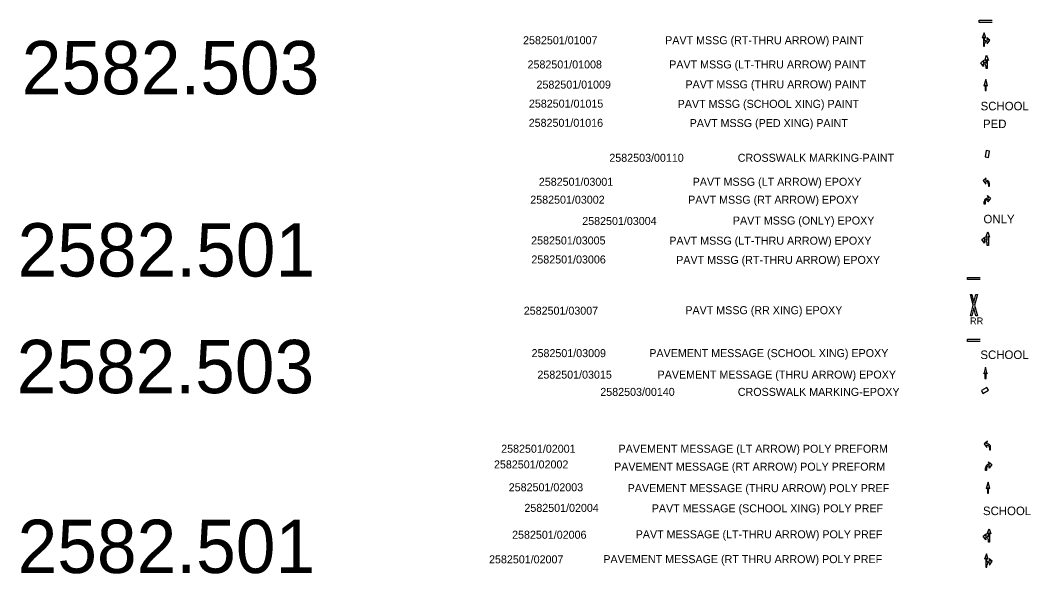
# Model space of a CAD drawing. Extents: x 2147716 to 2176321, y 2125040 to 2131750.
# Drawn here: x 2155871 to 2156818, y 2127335 to 2127855 of the extents above; entities that cross this region are included whole.
import ezdxf

# ---------------------------------------------------------------- set-up
doc = ezdxf.new("R2010")
doc.units = 0
doc.layers.add('DETAIL TXT', color=7, linetype='Continuous')
doc.layers.add('PVMT MARK', color=7, linetype='Continuous')

msp = doc.modelspace()

# ---------------------------------------------------------------- linework, layer by layer
at = {"layer": 'PVMT MARK'}
for p, q in [((2156769.69, 2127854.56), (2156781.69, 2127854.56)), ((2156769.69, 2127852.56), (2156769.69, 2127854.56)), ((2156781.69, 2127852.56), (2156769.69, 2127852.56)), ((2156774.26, 2127842.85), (2156772.52, 2127837.89)), ((2156772.52, 2127837.89), (2156773.76, 2127838.88)), ((2156773.76, 2127838.88), (2156773.76, 2127830.28)), ((2156775.99, 2127837.89), (2156774.26, 2127842.85)), ((2156774.75, 2127834.91), (2156774.75, 2127838.88)), ((2156774.75, 2127838.88), (2156775.99, 2127837.89)), ((2156776.9, 2127834.41), (2156777.57, 2127834.41)), ((2156779.72, 2127835.74), (2156776.97, 2127838.05)), ((2156776.97, 2127838.05), (2156777.63, 2127835.98)), ((2156777.63, 2127835.98), (2156776.97, 2127835.98)), ((2156777.23, 2127832.26), (2156779.72, 2127835.74)), ((2156777.57, 2127834.41), (2156777.23, 2127832.26)), ((2156773.76, 2127830.28), (2156774.75, 2127830.28)), ((2156774.75, 2127830.28), (2156774.75, 2127832.26)), ((2156771.22, 2127814.69), (2156773.96, 2127817)), ((2156773.96, 2127817), (2156773.3, 2127814.94)), ((2156774.94, 2127816.84), (2156776.67, 2127821.8)), ((2156776.18, 2127817.83), (2156774.94, 2127816.84)), ((2156776.18, 2127813.86), (2156776.18, 2127817.83)), ((2156776.67, 2127821.8), (2156778.41, 2127816.84)), ((2156778.41, 2127816.84), (2156777.17, 2127817.83)), ((2156777.17, 2127817.83), (2156777.17, 2127809.23)), ((2156773.7, 2127811.22), (2156771.22, 2127814.69)), ((2156773.3, 2127814.94), (2156773.96, 2127814.94)), ((2156774.03, 2127813.37), (2156773.37, 2127813.37)), ((2156773.37, 2127813.37), (2156773.7, 2127811.22)), ((2156776.18, 2127809.23), (2156776.18, 2127811.22)), ((2156777.17, 2127809.23), (2156776.18, 2127809.23)), ((2156774.14, 2127792.88), (2156775.26, 2127794.01)), ((2156775.26, 2127794.01), (2156775.26, 2127788.55)), ((2156775.26, 2127788.55), (2156776.25, 2127788.55)), ((2156776.25, 2127788.55), (2156776.25, 2127794.01)), ((2156776.25, 2127794.01), (2156777.37, 2127792.93)), ((2156776.28, 2127706.86), (2156773.3, 2127704.38)), ((2156773.3, 2127704.38), (2156775.78, 2127700.91)), ((2156775.38, 2127704.58), (2156776.28, 2127706.86)), ((2156776.04, 2127704.58), (2156775.38, 2127704.58)), ((2156775.78, 2127700.91), (2156775.38, 2127703.02)), ((2156775.38, 2127703.02), (2156776.04, 2127703.02)), ((2156778.26, 2127700.91), (2156778.26, 2127698.92)), ((2156778.26, 2127698.92), (2156779.26, 2127698.92)), ((2156779.26, 2127698.92), (2156779.26, 2127701.4)), ((2156774.4, 2127682.12), (2156774.4, 2127684.6)), ((2156775.39, 2127684.11), (2156775.39, 2127682.12)), ((2156778.28, 2127687.78), (2156777.37, 2127690.06)), ((2156777.37, 2127690.06), (2156780.35, 2127687.58)), ((2156777.62, 2127687.78), (2156778.28, 2127687.78)), ((2156778.28, 2127686.22), (2156777.62, 2127686.22)), ((2156780.35, 2127687.58), (2156777.87, 2127684.11)), ((2156777.87, 2127684.11), (2156778.28, 2127686.22)), ((2156775.39, 2127682.12), (2156774.4, 2127682.12)), ((2156776.01, 2127651.05), (2156777.75, 2127656.01)), ((2156777.75, 2127656.01), (2156779.48, 2127651.05)), ((2156772.29, 2127648.9), (2156775.03, 2127651.21)), ((2156774.77, 2127645.42), (2156772.29, 2127648.9)), ((2156775.03, 2127651.21), (2156774.37, 2127649.14)), ((2156774.37, 2127649.14), (2156775.03, 2127649.14)), ((2156775.1, 2127647.57), (2156774.44, 2127647.57)), ((2156774.44, 2127647.57), (2156774.77, 2127645.42)), ((2156777.25, 2127652.04), (2156776.01, 2127651.05)), ((2156777.25, 2127648.07), (2156777.25, 2127652.04)), ((2156777.25, 2127643.44), (2156777.25, 2127645.42)), ((2156779.48, 2127651.05), (2156778.24, 2127652.04)), ((2156778.24, 2127652.04), (2156778.24, 2127643.44)), ((2156778.24, 2127643.44), (2156777.25, 2127643.44)), ((2156758.67, 2127613.32), (2156770.67, 2127613.32)), ((2156758.67, 2127611.32), (2156758.67, 2127613.32)), ((2156770.67, 2127611.32), (2156758.67, 2127611.32)), ((2156761.47, 2127597.32), (2156764.07, 2127587.32)), ((2156764.07, 2127587.32), (2156761.47, 2127597.32)), ((2156764.07, 2127587.32), (2156761.47, 2127597.32)), ((2156761.47, 2127597.32), (2156762.77, 2127597.32)), ((2156762.77, 2127597.32), (2156764.67, 2127589.82)), ((2156764.67, 2127589.82), (2156766.67, 2127597.32)), ((2156767.97, 2127597.32), (2156765.37, 2127587.32)), ((2156766.67, 2127597.32), (2156767.97, 2127597.32)), ((2156761.47, 2127577.32), (2156764.07, 2127587.32)), ((2156764.67, 2127584.82), (2156762.77, 2127577.32)), ((2156764.67, 2127587.32), (2156764.67, 2127587.32)), ((2156766.67, 2127577.32), (2156764.67, 2127584.82)), ((2156765.37, 2127587.32), (2156767.97, 2127577.32)), ((2156762.77, 2127577.32), (2156761.47, 2127577.32)), ((2156767.97, 2127577.32), (2156766.67, 2127577.32)), ((2156758.67, 2127555.32), (2156770.67, 2127555.32)), ((2156758.67, 2127553.32), (2156758.67, 2127555.32)), ((2156770.67, 2127553.32), (2156758.67, 2127553.32)), ((2156773.95, 2127523.01), (2156775.07, 2127524.13)), ((2156775.07, 2127524.13), (2156775.07, 2127518.67)), ((2156776.06, 2127518.67), (2156776.06, 2127524.13)), ((2156776.06, 2127524.13), (2156777.19, 2127523.06)), ((2156775.07, 2127518.67), (2156776.06, 2127518.67)), ((2156777.41, 2127459.69), (2156774.44, 2127457.21)), ((2156774.44, 2127457.21), (2156776.92, 2127453.74)), ((2156776.51, 2127457.41), (2156777.41, 2127459.69)), ((2156777.17, 2127457.41), (2156776.51, 2127457.41)), ((2156776.92, 2127453.74), (2156776.51, 2127455.86)), ((2156776.51, 2127455.86), (2156777.17, 2127455.86)), ((2156779.4, 2127453.74), (2156779.4, 2127451.75)), ((2156779.4, 2127451.75), (2156780.39, 2127451.75)), ((2156780.39, 2127451.75), (2156780.39, 2127454.23)), ((2156779.41, 2127438.09), (2156778.51, 2127440.37)), ((2156778.51, 2127440.37), (2156781.48, 2127437.89)), ((2156778.75, 2127438.09), (2156779.41, 2127438.09)), ((2156779.41, 2127436.54), (2156778.75, 2127436.54)), ((2156781.48, 2127437.89), (2156779, 2127434.42)), ((2156779, 2127434.42), (2156779.41, 2127436.54)), ((2156775.53, 2127432.43), (2156775.53, 2127434.91)), ((2156776.52, 2127432.43), (2156775.53, 2127432.43)), ((2156776.52, 2127434.42), (2156776.52, 2127432.43)), ((2156776.34, 2127415.28), (2156777.46, 2127416.4)), ((2156777.46, 2127416.4), (2156777.46, 2127410.94)), ((2156777.46, 2127410.94), (2156778.46, 2127410.94)), ((2156778.46, 2127410.94), (2156778.46, 2127416.4)), ((2156778.46, 2127416.4), (2156779.58, 2127415.33)), ((2156773.42, 2127370.65), (2156776.17, 2127372.96)), ((2156775.9, 2127367.17), (2156773.42, 2127370.65)), ((2156776.17, 2127372.96), (2156775.51, 2127370.9)), ((2156775.51, 2127370.9), (2156776.17, 2127370.9)), ((2156777.14, 2127372.8), (2156778.88, 2127377.76)), ((2156778.38, 2127373.79), (2156777.14, 2127372.8)), ((2156778.38, 2127369.82), (2156778.38, 2127373.79)), ((2156778.88, 2127377.76), (2156780.62, 2127372.8)), ((2156780.62, 2127372.8), (2156779.37, 2127373.79)), ((2156779.37, 2127373.79), (2156779.37, 2127365.19)), ((2156776.23, 2127369.32), (2156775.57, 2127369.32)), ((2156775.57, 2127369.32), (2156775.9, 2127367.17)), ((2156778.38, 2127365.19), (2156778.38, 2127367.17)), ((2156779.37, 2127365.19), (2156778.38, 2127365.19)), ((2156776.46, 2127354.29), (2156774.73, 2127349.32)), ((2156778.2, 2127349.32), (2156776.46, 2127354.29)), ((2156774.73, 2127349.32), (2156775.97, 2127350.32)), ((2156775.97, 2127350.32), (2156775.97, 2127341.72)), ((2156775.97, 2127341.72), (2156776.96, 2127341.72)), ((2156776.96, 2127346.35), (2156776.96, 2127350.32)), ((2156776.96, 2127350.32), (2156778.2, 2127349.32)), ((2156776.96, 2127341.72), (2156776.96, 2127343.7)), ((2156779.11, 2127345.85), (2156779.77, 2127345.85)), ((2156781.92, 2127347.17), (2156779.17, 2127349.49)), ((2156779.17, 2127349.49), (2156779.84, 2127347.42)), ((2156779.84, 2127347.42), (2156779.17, 2127347.42)), ((2156779.44, 2127343.7), (2156781.92, 2127347.17)), ((2156779.77, 2127345.85), (2156779.44, 2127343.7))]:
    msp.add_line(p, q, dxfattribs=at)
for points in [[(2156777.37, 2127792.93), (2156775.76, 2127799.01), (2156774.14, 2127792.93)], [(2156777.19, 2127523.06), (2156775.57, 2127529.14), (2156773.95, 2127523.06)], [(2156779.58, 2127415.33), (2156777.96, 2127421.41), (2156776.34, 2127415.33)]]:
    msp.add_lwpolyline(points, dxfattribs=at)
for points in [[(2156775.37, 2127726.32), (2156778.33, 2127725.83), (2156779.31, 2127731.75), (2156776.35, 2127732.24)], [(2156778.43, 2127507.6), (2156776.97, 2127510.22), (2156771.73, 2127507.31), (2156773.18, 2127504.68)]]:
    msp.add_lwpolyline(points, close=True, dxfattribs=at)
for radius in [0.04, 0.035]:
    msp.add_circle((2156764.67, 2127587.32), radius, dxfattribs=at)
for centre, radius, start, end in [((2156777.16, 2127832.76), 3.23, 93.44933, 138.32895), ((2156776.9, 2127832.26), 2.15, 90, 180), ((2156773.77, 2127811.72), 3.23, 41.67105, 86.55067), ((2156774.03, 2127811.22), 2.15, 0, 90), ((2156776.03, 2127701.35), 3.22, 0.85489, 89.91229), ((2156776.11, 2127700.88), 2.15, 0.74176, 90.20562), ((2156777.62, 2127684.55), 3.22, 90.08771, 179.14511), ((2156777.54, 2127684.08), 2.15, 89.79438, 179.25824), ((2156774.84, 2127645.92), 3.23, 41.67105, 86.55067), ((2156775.1, 2127645.42), 2.15, 0, 90), ((2156777.17, 2127454.19), 3.22, 0.85489, 89.91229), ((2156777.25, 2127453.71), 2.15, 0.74176, 90.20562), ((2156778.75, 2127434.87), 3.22, 90.08771, 179.14511), ((2156778.67, 2127434.39), 2.15, 89.79438, 179.25824), ((2156775.97, 2127367.68), 3.23, 41.67105, 86.55067), ((2156776.23, 2127367.17), 2.15, 0, 90), ((2156779.37, 2127344.2), 3.23, 93.44933, 138.32895), ((2156779.11, 2127343.7), 2.15, 90, 180)]:
    msp.add_arc(centre, radius, start, end, dxfattribs=at)

# ---------------------------------------------------------------- texts
at = {"layer": 'DETAIL TXT'}
for s, height, p in [('2582.503', 50, (2155872.33, 2127785.05)), ('2582501/01007', 7.5, (2156342.17, 2127832.02)), ('PAVT MSSG (RT-THRU ARROW) PAINT', 7.5, (2156475.35, 2127832.02)), ('2582501/01008', 7.5, (2156346.35, 2127809.34)), ('PAVT MSSG (LT-THRU ARROW) PAINT', 7.5, (2156479.13, 2127809.34)), ('2582501/01009', 7.5, (2156354.76, 2127790.44)), ('PAVT MSSG (THRU ARROW) PAINT', 7.5, (2156494.37, 2127790.65)), ('2582501/01015', 7.5, (2156347.63, 2127772.59)), ('PAVT MSSG (SCHOOL XING) PAINT', 7.5, (2156487.05, 2127772.38)), ('2582501/01016', 7.5, (2156347.44, 2127754.59)), ('PAVT MSSG (PED XING) PAINT', 7.5, (2156498.3, 2127754.38)), ('2582503/00110', 7.5, (2156423.01, 2127721.8)), ('CROSSWALK MARKING-PAINT', 7.5, (2156543.36, 2127721.8)), ('2582501/03001', 7.5, (2156356.93, 2127699.3)), ('PAVT MSSG (LT ARROW) EPOXY', 7.5, (2156501.13, 2127699.3)), ('2582501/03002', 7.5, (2156348.89, 2127682.5)), ('PAVT MSSG (RT ARROW) EPOXY', 7.5, (2156496.93, 2127682.5)), ('2582.501', 50, (2155868.37, 2127614.21)), ('2582501/03004', 7.5, (2156397.6, 2127662.55)), ('PAVT MSSG (ONLY) EPOXY', 7.5, (2156538.81, 2127662.97)), ('2582501/03005', 7.5, (2156349.73, 2127644.28)), ('PAVT MSSG (LT-THRU ARROW) EPOXY', 7.5, (2156479.23, 2127644.07)), ('2582501/03006', 7.5, (2156349.96, 2127626.45)), ('PAVT MSSG (RT-THRU ARROW) EPOXY', 7.5, (2156485.7, 2127626.02)), ('2582501/03007', 7.5, (2156342.8, 2127578.43)), ('PAVT MSSG (RR XING) EPOXY', 7.5, (2156494.27, 2127578.9)), ('2582.503', 50, (2155867.47, 2127504.81)), ('2582501/03009', 7.5, (2156350.14, 2127538.62)), ('PAVEMENT MESSAGE (SCHOOL XING) EPOXY', 7.5, (2156460.48, 2127538.65)), ('2582501/03015', 7.5, (2156355.61, 2127518.46)), ('PAVEMENT MESSAGE (THRU ARROW) EPOXY', 7.5, (2156468.22, 2127518.49)), ('2582503/00140', 7.5, (2156414.55, 2127502.29)), ('CROSSWALK MARKING-EPOXY', 7.5, (2156543.46, 2127502.29)), ('2582501/02001', 7.5, (2156321.65, 2127448.98)), ('PAVEMENT MESSAGE (LT ARROW) POLY PREFORM', 7.5, (2156431.66, 2127448.98)), ('2582501/02002', 7.5, (2156314.88, 2127434.28)), ('PAVEMENT MESSAGE (RT ARROW) POLY PREFORM', 7.5, (2156427.46, 2127432.18)), ('2582501/02003', 7.5, (2156328.73, 2127412.86)), ('PAVEMENT MESSAGE (THRU ARROW) POLY PREF', 7.5, (2156440.18, 2127412.02)), ('2582501/02004', 7.5, (2156343.42, 2127393.54)), ('PAVT MESSAGE (SCHOOL XING) POLY PREF', 7.5, (2156462.77, 2127393.12)), ('2582.501', 50, (2155868.37, 2127336.18)), ('2582501/02006', 7.5, (2156331.87, 2127368.34)), ('PAVT MESSAGE (LT-THRU ARROW) POLY PREF', 7.5, (2156447.71, 2127368.76)), ('2582501/02007', 7.5, (2156310.25, 2127345.25)), ('PAVEMENT MESSAGE (RT THRU ARROW) POLY PREF', 7.5, (2156417.38, 2127345.46))]:
    msp.add_text(s, height=height, dxfattribs=at).set_placement(p)
at = {"layer": 'PVMT MARK'}
for s, p in [('PERIMETER 50FT', (2156777.17, 2127835.11)), ('AREA 26 SQ FT', (2156777.28, 2127835.56)), ('REM 95 SQ FT', (2156777.34, 2127835.35)), ("PERIMETER = 30 '", (2156776.14, 2127686.42)), ("REM = 48 SQ '", (2156776.4, 2127686.74)), ("AREA = 15 SQ'", (2156776.5, 2127687.07)), ("PERIMETER = 30 '", (2156777.27, 2127436.73)), ("REM = 48 SQ '", (2156777.53, 2127437.06)), ("AREA = 15 SQ'", (2156777.63, 2127437.38)), ('PERIMETER 50FT', (2156779.38, 2127346.55)), ('AREA 26 SQ FT', (2156779.49, 2127347)), ('REM 95 SQ FT', (2156779.55, 2127346.79))]:
    msp.add_text(s, height=0.0992, rotation=360, dxfattribs=at).set_placement(p)
for s, height, p in [('AREA 26 SQ FT', 0.0992, (2156772.45, 2127814.51)), ('REM 95 SQ FT', 0.0992, (2156772.48, 2127814.3)), ('PERIMETER 50FT', 0.0992, (2156772.51, 2127814.06)), ('PERIMETER 30 FT', 0.0907, (2156775, 2127794.65)), ('REM 35 SF', 0.0907, (2156775.24, 2127794.99)), ('AREA 15 SF', 0.0907, (2156775.33, 2127795.29)), ('SCHOOL', 8, (2156771, 2127770.05)), ('PED', 8, (2156773.22, 2127753.38)), ("AREA = 15 SQ'", 0.0992, (2156776.09, 2127703.95)), ("REM = 48 SQ '", 0.0992, (2156776.14, 2127703.62)), ("PERIMETER = 30 '", 0.0992, (2156776.16, 2127703.3)), ('ONLY', 8, (2156773.68, 2127664.11)), ('AREA 26 SQ FT', 0.0992, (2156773.53, 2127648.72)), ('REM 95 SQ FT', 0.0992, (2156773.55, 2127648.51)), ('PERIMETER 50FT', 0.0992, (2156773.58, 2127648.27)), ('RR', 6.5, (2156760.97, 2127569.32)), ('SCHOOL', 8, (2156770.82, 2127536.85)), ('PERIMETER 30 FT', 0.0907, (2156774.81, 2127524.77)), ('REM 35 SF', 0.0907, (2156775.05, 2127525.12)), ('AREA 15 SF', 0.0907, (2156775.14, 2127525.42)), ("AREA = 15 SQ'", 0.0992, (2156777.22, 2127456.78)), ("REM = 48 SQ '", 0.0992, (2156777.27, 2127456.45)), ("PERIMETER = 30 '", 0.0992, (2156777.3, 2127456.13)), ('REM 35 SF', 0.0907, (2156777.45, 2127417.39)), ('AREA 15 SF', 0.0907, (2156777.53, 2127417.69)), ('PERIMETER 30 FT', 0.0907, (2156777.2, 2127417.05)), ('SCHOOL', 8, (2156773.21, 2127390.48)), ('AREA 26 SQ FT', 0.0992, (2156774.66, 2127370.47)), ('REM 95 SQ FT', 0.0992, (2156774.69, 2127370.26)), ('PERIMETER 50FT', 0.0992, (2156774.72, 2127370.02))]:
    msp.add_text(s, height=height, dxfattribs=at).set_placement(p)

doc.saveas('drawing.dxf')
